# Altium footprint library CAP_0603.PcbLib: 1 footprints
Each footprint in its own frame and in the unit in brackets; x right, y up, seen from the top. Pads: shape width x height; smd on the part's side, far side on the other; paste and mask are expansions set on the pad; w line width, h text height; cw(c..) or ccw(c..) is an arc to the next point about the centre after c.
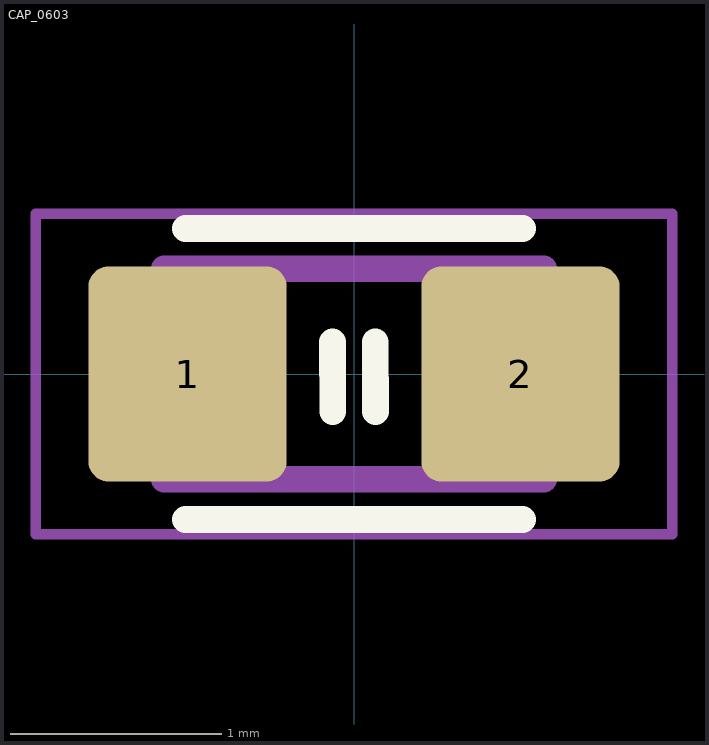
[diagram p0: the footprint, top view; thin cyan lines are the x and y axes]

## CAP_0603 [mm]
pads (2):
  rrect20% 0.94x1.02 smd: 1(-0.79,0) 2(0.79,0)
Top Overlay:
  lines w0.127: -0.8,-0.69 0.8,-0.69 ; -0.8,0.69 0.8,0.69 ; -0.101,-0.178 -0.102,0.152 ; 0.102,-0.178 0.101,0.152
Mechanical 13:
  lines w0.127: -0.9,-0.5 0.9,-0.5 0.9,0.5 -0.9,0.5 -0.9,-0.5
Mechanical 15:
  lines w0.05: -1.51,-0.76 1.51,-0.76 1.51,0.76 -1.51,0.76 -1.51,-0.76
3D body "CAP_0603.STEP": height 0.81, standoff 0, extent -0.81,-0.45 0.79,0.45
